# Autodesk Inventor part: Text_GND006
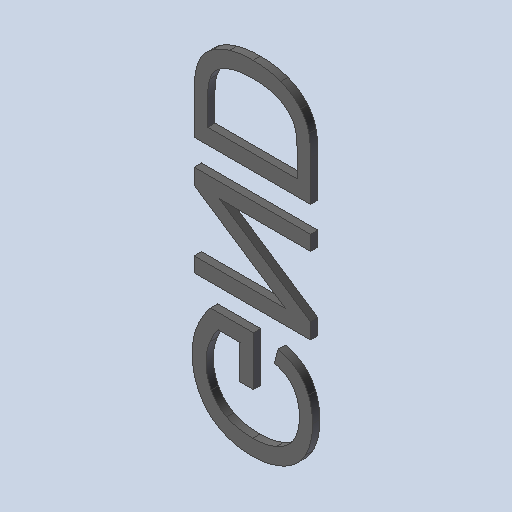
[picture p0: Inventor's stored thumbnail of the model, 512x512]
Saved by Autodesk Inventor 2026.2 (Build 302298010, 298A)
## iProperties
Created: 2026-10
Part Number: Text_GND006
Material: Générique
Document SubType Name: Modeling
Designer: mel
Density: 1 g/cm^3
Appearance: Par défaut
Author: mel
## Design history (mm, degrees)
feature "Base1"
feature "Base2"
feature "Base3"
node "Solide1"
node "Solide2"
node "Solide3"
